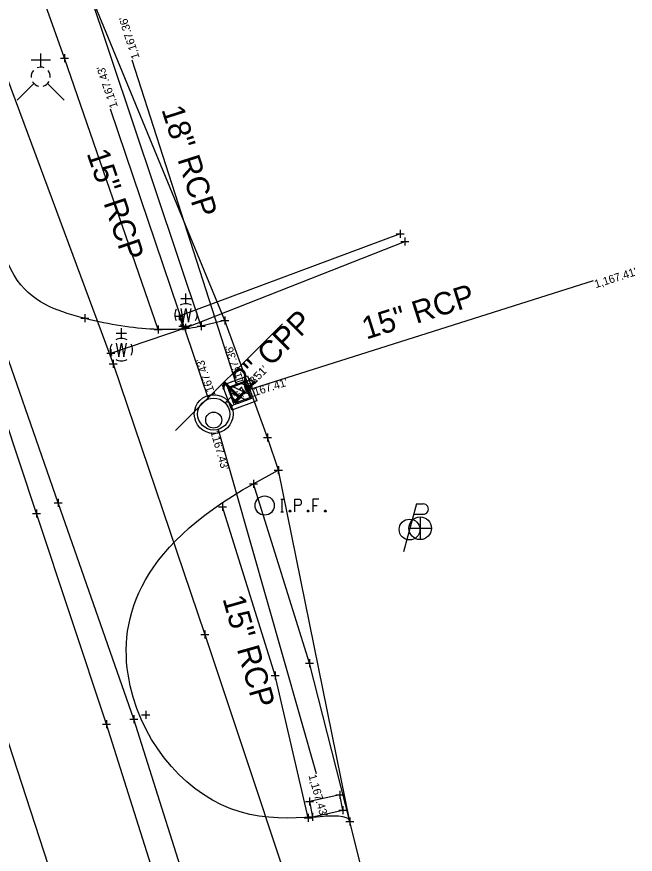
# Model space of a CAD drawing. Extents: x 2324380 to 2325559, y 691096 to 693386.
# Drawn here: x 2325067.6 to 2325144.8, y 692170 to 692274.6 of the extents above; entities that cross this region are included whole.
import ezdxf

# ---------------------------------------------------------------- set-up
doc = ezdxf.new("R2010")
doc.units = 0
for name, color, linetype in [('DR_X_Cells', 7, 'Continuous'), ('DR_X_Storm_Sewer', 7, 'Continuous'), ('DR_X_Text', 7, 'Continuous'), ('GK_Drainage_Nodes', 7, 'Continuous'), ('PM_X_CL_Double_Solid', 7, 'Continuous'), ('PM_X_Transverse_Line', 7, 'Continuous'), ('PV_X_COP', 7, 'Continuous'), ('PV_X_Driveway', 7, 'Continuous'), ('PV_X_EOP', 7, 'Continuous'), ('PV_X_Walk', 7, 'Continuous'), ('RD_X_Concrete_Pad', 7, 'Continuous'), ('SC_Scratch1', 7, 'Continuous'), ('SV_X_Control_Cells_Found', 7, 'Continuous'), ('SV_X_Mon_Cells_Found', 7, 'Continuous'), ('SV_X_Shot_Marker', 7, 'Continuous'), ('SV_X_Terrain_Boundary', 7, 'Continuous'), ('UT_X_Electric_Cells', 7, 'Continuous'), ('UT_X_Water', 7, 'Continuous'), ('UT_X_Water_Cells', 7, 'Continuous')]:
    doc.layers.add(name, color=color, linetype=linetype)

msp = doc.modelspace()

# ---------------------------------------------------------------- linework, layer by layer
at = {"layer": 'DR_X_Cells'}
for p, q in [((2325094.44, 692228.44), (2325096.7, 692227.4)), ((2325095.5, 692228.83), (2325096.3, 692228.46)), ((2325094.14, 692227.69), (2325096.32, 692226.69)), ((2325094.54, 692226.63), (2325095.26, 692226.3))]:
    msp.add_line(p, q, dxfattribs=at)
for points in [[(2325096.39, 692229.72), (2325097.55, 692226.59), (2325094.43, 692225.43), (2325093.27, 692228.56)], [(2325096.08, 692229.05), (2325096.88, 692226.9), (2325094.73, 692226.1), (2325093.94, 692228.25)], [(2325096, 692228.86), (2325096.69, 692226.98), (2325094.82, 692226.29), (2325094.12, 692228.16)]]:
    msp.add_lwpolyline(points, close=True, dxfattribs=at)
for centre, radius in [((2325092.18, 692224.94), 2.42), ((2325092.18, 692224.94), 2), ((2325092.18, 692224.19), 1)]:
    msp.add_circle(centre, radius, dxfattribs=at)
at = {"layer": 'DR_X_Storm_Sewer'}
for p, q in [((2325095.06, 692228.51), (2325081.99, 692269.16)), ((2325091.54, 692226.83), (2325079.28, 692263.03)), ((2325096.35, 692227.92), (2325139.58, 692241.61)), ((2325093.6, 692226.35), (2325094.47, 692227.23)), ((2325092.73, 692223.02), (2325104.96, 692180.06))]:
    msp.add_line(p, q, dxfattribs=at)
at = {"layer": 'DR_X_Text'}
msp.add_line((2325100.78, 692236.22), (2325087.43, 692222.88), dxfattribs=at)
at = {"layer": 'GK_Drainage_Nodes'}
for p, q in [((2325095.06, 692228.51), (2325095.06, 692228.51)), ((2325096.97, 692228.15), (2325096.97, 692228.15)), ((2325094.47, 692227.23), (2325094.47, 692227.23)), ((2325095.41, 692227.57), (2325095.41, 692227.57)), ((2325095.41, 692227.57), (2325095.41, 692227.57)), ((2325095.41, 692227.57), (2325095.41, 692227.57)), ((2325096.35, 692227.92), (2325096.35, 692227.92)), ((2325092.18, 692226.94), (2325092.18, 692226.94)), ((2325093.85, 692226.99), (2325093.85, 692226.99)), ((2325095.76, 692226.64), (2325095.76, 692226.64)), ((2325092.18, 692224.94), (2325092.18, 692224.94)), ((2325092.18, 692224.94), (2325092.18, 692224.94)), ((2325092.18, 692224.19), (2325092.18, 692224.19)), ((2325092.18, 692222.94), (2325092.18, 692222.94))]:
    msp.add_line(p, q, dxfattribs=at)
msp.add_circle((2325092.18, 692224.94), 2, dxfattribs=at)
at = {"layer": 'PM_X_CL_Double_Solid'}
msp.add_lwpolyline([(2325089.48, 692110.68), (2325084.32, 692128.51), (2325075.39, 692156.76), (2325066.63, 692183.78), (2325058.11, 692209.28), (2325049.62, 692233.9), (2325041.55, 692256.48), (2325033.1, 692279.67), (2325023.32, 692305.87), (2325013.77, 692329.93)], dxfattribs=at)
at = {"layer": 'PM_X_Transverse_Line'}
msp.add_lwpolyline([(2325119.99, 692049.57), (2325112.24, 692077.64), (2325103.35, 692107.53), (2325096.49, 692131.33), (2325087.35, 692159.17), (2325078.82, 692186.21), (2325070.07, 692212.52), (2325061.8, 692237.43), (2325045.09, 692283.67), (2325035.69, 692308.59), (2325025.65, 692334.45)], dxfattribs=at)
at = {"layer": 'PV_X_COP'}
msp.add_lwpolyline([(2325108.45, 692046.03), (2325099.34, 692075.66), (2325091, 692105.35), (2325084.32, 692128.51), (2325075.39, 692156.76), (2325066.63, 692183.78), (2325058.11, 692209.28), (2325049.62, 692233.9), (2325041.55, 692256.48), (2325033.1, 692279.67), (2325023.32, 692305.87), (2325013.77, 692329.93)], dxfattribs=at)
at = {"layer": 'PV_X_Driveway'}
for p, q in [((2325093.57, 692236.62), (2325090.6, 692235.9)), ((2325098.88, 692222), (2325093.57, 692236.62)), ((2325100.28, 692217.91), (2325098.88, 692222)), ((2325097.15, 692216.23), (2325100.24, 692217.94)), ((2325100.24, 692217.94), (2325100.28, 692217.91)), ((2325110.91, 692166.99), (2325109.19, 692174.04))]:
    msp.add_line(p, q, dxfattribs=at)
for points in [[(2325090.6, 692235.9), (2325088.84, 692235.48), (2325083.93, 692235.28), (2325075.21, 692236.84), (2325065.59, 692240.39), (2325064.41, 692252.96), (2325061.43, 692251.66)], [(2325109.19, 692174.04), (2325108.77, 692175.78), (2325094.85, 692170.95), (2325077.79, 692189.42), (2325082.29, 692208.02), (2325097.15, 692216.23)]]:
    msp.add_open_spline(points, degree=3, dxfattribs=at)
at = {"layer": 'PV_X_EOP'}
msp.add_lwpolyline([(2325123.25, 692051.46), (2325115.82, 692078.51), (2325110.86, 692095.71), (2325106.46, 692109.57), (2325099.73, 692132.13), (2325090.5, 692160.58), (2325082.22, 692186.84), (2325072.77, 692213.83), (2325064.19, 692238.4), (2325059.92, 692251), (2325055.34, 692262.57), (2325047.32, 692284.59), (2325037.78, 692309.71), (2325028.4, 692335.51)], dxfattribs=at)
at = {"layer": 'PV_X_Walk'}
for points in [[(2325090.6, 692235.9), (2325076.53, 692278.08), (2325068.46, 692300.04), (2325060.86, 692317.44), (2325050.46, 692344.77)], [(2325085.26, 692235.48), (2325073.57, 692269.38), (2325065.48, 692291.96), (2325056.49, 692315.71), (2325046.07, 692343.18)], [(2325109.19, 692174.04), (2325104.12, 692193.82), (2325097.15, 692216.23)], [(2325103.96, 692174.49), (2325099.86, 692192.28), (2325093.3, 692213.33)]]:
    msp.add_lwpolyline(points, dxfattribs=at)
at = {"layer": 'RD_X_Concrete_Pad'}
msp.add_lwpolyline([(2325104.13, 692176.55), (2325104.52, 692174.62), (2325108.32, 692175.44), (2325107.94, 692177.39)], close=True, dxfattribs=at)
at = {"layer": 'SV_X_Control_Cells_Found'}
for p, q in [((2325117.96, 692212.08), (2325117.96, 692209.26)), ((2325116.55, 692210.67), (2325119.37, 692210.67))]:
    msp.add_line(p, q, dxfattribs=at)
msp.add_circle((2325117.96, 692210.67), 1.41, dxfattribs=at)
at = {"layer": 'SV_X_Mon_Cells_Found'}
for points in [[(2325100.55, 692214.31), (2325100.91, 692214.31)], [(2325100.73, 692212.71), (2325100.73, 692214.31)], [(2325102.3, 692212.71), (2325102.3, 692214.31), (2325102.83, 692214.31), (2325102.88, 692214.29), (2325102.96, 692214.27), (2325102.99, 692214.24), (2325103.02, 692214.22), (2325103.07, 692214.16), (2325103.1, 692214.09), (2325103.12, 692213.99), (2325103.12, 692213.84), (2325103.11, 692213.79), (2325103.09, 692213.71), (2325103.05, 692213.63), (2325103, 692213.59), (2325102.97, 692213.56), (2325102.91, 692213.54), (2325102.83, 692213.53), (2325102.3, 692213.53)], [(2325105.31, 692214.31), (2325104.54, 692214.31), (2325104.54, 692212.71)], [(2325104.54, 692213.53), (2325105.08, 692213.53)], [(2325100.55, 692212.71), (2325100.91, 692212.71)], [(2325101.69, 692212.92), (2325101.74, 692212.92), (2325101.78, 692212.9), (2325101.81, 692212.84), (2325101.81, 692212.78), (2325101.78, 692212.73), (2325101.74, 692212.71), (2325101.69, 692212.71), (2325101.66, 692212.73), (2325101.62, 692212.78), (2325101.62, 692212.84), (2325101.66, 692212.9), (2325101.69, 692212.92)], [(2325103.94, 692212.92), (2325103.99, 692212.92), (2325104.03, 692212.9), (2325104.06, 692212.84), (2325104.06, 692212.78), (2325104.03, 692212.73), (2325103.99, 692212.71), (2325103.94, 692212.71), (2325103.91, 692212.73), (2325103.87, 692212.78), (2325103.87, 692212.84), (2325103.91, 692212.9), (2325103.94, 692212.92)], [(2325106.09, 692212.92), (2325106.14, 692212.92), (2325106.18, 692212.9), (2325106.21, 692212.84), (2325106.21, 692212.78), (2325106.18, 692212.73), (2325106.14, 692212.71), (2325106.09, 692212.71), (2325106.05, 692212.73), (2325106.02, 692212.78), (2325106.02, 692212.84), (2325106.05, 692212.9), (2325106.09, 692212.92)]]:
    msp.add_lwpolyline(points, dxfattribs=at)
msp.add_circle((2325098.54, 692213.51), 1.2, dxfattribs=at)
at = {"layer": 'SV_X_Shot_Marker'}
for p, q in [((2325073.07, 692269.38), (2325074.07, 692269.38)), ((2325073.57, 692269.88), (2325073.57, 692268.88)), ((2325073.57, 692269.38), (2325073.57, 692269.38)), ((2325114.95, 692247.46), (2325115.95, 692247.46)), ((2325115.45, 692247.96), (2325115.45, 692246.96)), ((2325115.45, 692247.46), (2325115.45, 692247.46)), ((2325115.52, 692246.48), (2325116.52, 692246.48)), ((2325116.02, 692246.98), (2325116.02, 692245.98)), ((2325116.02, 692246.48), (2325116.02, 692246.48)), ((2325087.89, 692237.67), (2325087.89, 692236.67)), ((2325075.6, 692236.93), (2325076.6, 692236.93)), ((2325076.1, 692237.43), (2325076.1, 692236.43)), ((2325076.1, 692236.93), (2325076.1, 692236.93)), ((2325087.39, 692237.17), (2325088.39, 692237.17)), ((2325087.89, 692237.17), (2325087.89, 692237.17)), ((2325093.07, 692236.62), (2325094.07, 692236.62)), ((2325093.57, 692237.12), (2325093.57, 692236.12)), ((2325093.57, 692236.62), (2325093.57, 692236.62)), ((2325084.76, 692235.48), (2325085.76, 692235.48)), ((2325084.76, 692235.48), (2325085.76, 692235.48)), ((2325085.26, 692235.98), (2325085.26, 692234.98)), ((2325085.26, 692235.98), (2325085.26, 692234.98)), ((2325085.26, 692235.48), (2325085.26, 692235.48)), ((2325085.26, 692235.48), (2325085.26, 692235.48)), ((2325087.83, 692235.92), (2325088.83, 692235.92)), ((2325088.15, 692235.72), (2325089.15, 692235.72)), ((2325088.33, 692236.42), (2325088.33, 692235.42)), ((2325088.33, 692235.92), (2325088.33, 692235.92)), ((2325088.65, 692236.22), (2325088.65, 692235.22)), ((2325088.65, 692235.72), (2325088.65, 692235.72)), ((2325090.1, 692235.9), (2325091.1, 692235.9)), ((2325090.1, 692235.9), (2325091.1, 692235.9)), ((2325090.6, 692236.4), (2325090.6, 692235.4)), ((2325090.6, 692236.4), (2325090.6, 692235.4)), ((2325090.6, 692235.9), (2325090.6, 692235.9)), ((2325090.6, 692235.9), (2325090.6, 692235.9)), ((2325078.84, 692232.54), (2325079.84, 692232.54)), ((2325079.34, 692233.04), (2325079.34, 692232.04)), ((2325079.34, 692232.54), (2325079.34, 692232.54)), ((2325079.64, 692231.7), (2325079.64, 692230.7)), ((2325079.14, 692231.2), (2325080.14, 692231.2)), ((2325079.64, 692231.2), (2325079.64, 692231.2)), ((2325098.38, 692222), (2325099.38, 692222)), ((2325098.88, 692222.5), (2325098.88, 692221.5)), ((2325098.88, 692222), (2325098.88, 692222)), ((2325099.74, 692217.94), (2325100.74, 692217.94)), ((2325099.78, 692217.91), (2325100.78, 692217.91)), ((2325100.24, 692218.44), (2325100.24, 692217.44)), ((2325100.24, 692217.94), (2325100.24, 692217.94)), ((2325100.28, 692218.41), (2325100.28, 692217.41)), ((2325100.28, 692217.91), (2325100.28, 692217.91)), ((2325097.15, 692216.73), (2325097.15, 692215.73)), ((2325097.15, 692216.73), (2325097.15, 692215.73)), ((2325096.65, 692216.23), (2325097.65, 692216.23)), ((2325096.65, 692216.23), (2325097.65, 692216.23)), ((2325097.15, 692216.23), (2325097.15, 692216.23)), ((2325097.15, 692216.23), (2325097.15, 692216.23)), ((2325072.27, 692213.83), (2325073.27, 692213.83)), ((2325072.77, 692214.33), (2325072.77, 692213.33)), ((2325072.77, 692213.83), (2325072.77, 692213.83)), ((2325093.3, 692213.83), (2325093.3, 692212.83)), ((2325069.57, 692212.52), (2325070.57, 692212.52)), ((2325070.07, 692213.02), (2325070.07, 692212.02)), ((2325070.07, 692212.52), (2325070.07, 692212.52)), ((2325092.8, 692213.33), (2325093.8, 692213.33)), ((2325093.3, 692213.33), (2325093.3, 692213.33)), ((2325091.06, 692197.91), (2325091.06, 692196.91)), ((2325090.56, 692197.41), (2325091.56, 692197.41)), ((2325091.06, 692197.41), (2325091.06, 692197.41)), ((2325103.62, 692193.82), (2325104.62, 692193.82)), ((2325104.12, 692194.32), (2325104.12, 692193.32)), ((2325104.12, 692193.82), (2325104.12, 692193.82)), ((2325099.86, 692192.78), (2325099.86, 692191.78)), ((2325099.36, 692192.28), (2325100.36, 692192.28)), ((2325099.86, 692192.28), (2325099.86, 692192.28)), ((2325083.19, 692187.38), (2325084.19, 692187.38)), ((2325083.69, 692187.88), (2325083.69, 692186.88)), ((2325083.69, 692187.38), (2325083.69, 692187.38)), ((2325078.82, 692186.71), (2325078.82, 692185.71)), ((2325081.72, 692186.84), (2325082.72, 692186.84)), ((2325082.22, 692187.34), (2325082.22, 692186.34)), ((2325082.22, 692186.84), (2325082.22, 692186.84)), ((2325078.32, 692186.21), (2325079.32, 692186.21)), ((2325078.82, 692186.21), (2325078.82, 692186.21)), ((2325104.13, 692177.05), (2325104.13, 692176.05)), ((2325107.44, 692177.39), (2325108.44, 692177.39)), ((2325107.94, 692177.89), (2325107.94, 692176.89)), ((2325107.94, 692177.39), (2325107.94, 692177.39)), ((2325103.63, 692176.55), (2325104.63, 692176.55)), ((2325104.13, 692176.55), (2325104.13, 692176.55)), ((2325108.32, 692175.94), (2325108.32, 692174.94)), ((2325103.96, 692174.99), (2325103.96, 692173.99)), ((2325103.96, 692174.99), (2325103.96, 692173.99)), ((2325104.52, 692175.12), (2325104.52, 692174.12)), ((2325107.82, 692175.44), (2325108.82, 692175.44)), ((2325108.32, 692175.44), (2325108.32, 692175.44)), ((2325103.46, 692174.49), (2325104.46, 692174.49)), ((2325103.46, 692174.49), (2325104.46, 692174.49)), ((2325103.96, 692174.49), (2325103.96, 692174.49)), ((2325103.96, 692174.49), (2325103.96, 692174.49)), ((2325104.02, 692174.62), (2325105.02, 692174.62)), ((2325104.52, 692174.62), (2325104.52, 692174.62)), ((2325108.69, 692174.04), (2325109.69, 692174.04)), ((2325108.69, 692174.04), (2325109.69, 692174.04)), ((2325109.19, 692174.54), (2325109.19, 692173.54)), ((2325109.19, 692174.54), (2325109.19, 692173.54)), ((2325109.19, 692174.04), (2325109.19, 692174.04)), ((2325109.19, 692174.04), (2325109.19, 692174.04))]:
    msp.add_line(p, q, dxfattribs=at)
at = {"layer": 'SV_X_Terrain_Boundary'}
msp.add_lwpolyline([(2325110.91, 692166.99), (2325109.19, 692174.04), (2325100.28, 692217.91), (2325098.88, 692222), (2325093.57, 692236.62), (2325076.53, 692278.08), (2325068.46, 692300.04), (2325060.86, 692317.44), (2325050.46, 692344.77), (2325046.07, 692343.18), (2325028.4, 692335.51), (2325013.77, 692329.93), (2324997.75, 692325.76), (2324994.77, 692324.28), (2324978.96, 692319.34), (2325000.08, 692267.16), (2325014.61, 692222.14), (2325030.56, 692121.28)], dxfattribs=at)
at = {"layer": 'UT_X_Electric_Cells'}
for p, q in [((2325117.49, 692213.71), (2325115.88, 692207.71)), ((2325117.49, 692213.71), (2325118.34, 692213.71)), ((2325117.15, 692212.43), (2325118.34, 692212.43))]:
    msp.add_line(p, q, dxfattribs=at)
msp.add_circle((2325116.63, 692210.51), 1.3, dxfattribs=at)
msp.add_arc((2325118.35, 692213.07), 0.638, 268.8767, 91.1233, dxfattribs=at)
at = {"layer": 'UT_X_Water'}
for points in [[(2324934.92, 692571.2), (2324956.29, 692529.58), (2324976.21, 692488), (2324991.94, 692453.33), (2325012.4, 692405.82), (2325031.94, 692356.27), (2325051.28, 692307.99), (2325065.92, 692268.22), (2325079.64, 692231.2), (2325091.06, 692197.41), (2325105.98, 692152.66), (2325121.62, 692099.73), (2325124.52, 692091.67), (2325134.64, 692057.74)], [(2325115.45, 692247.46), (2325087.89, 692237.17), (2325088.33, 692235.92)], [(2325079.34, 692232.54), (2325088.65, 692235.72), (2325116.02, 692246.48)]]:
    msp.add_lwpolyline(points, dxfattribs=at)
at = {"layer": 'UT_X_Water_Cells'}
for p, q in [((2325071.79, 692269.13), (2325069.39, 692269.13)), ((2325070.59, 692268.27), (2325070.59, 692269.99)), ((2325070.59, 692267.07), (2325070.59, 692267.07)), ((2325070.59, 692267.07), (2325070.59, 692267.07)), ((2325069.74, 692266.22), (2325067.66, 692264.14)), ((2325071.43, 692266.22), (2325073.51, 692264.14)), ((2325088.71, 692238.72), (2325088.71, 692239.99)), ((2325089.35, 692239.35), (2325088.08, 692239.35)), ((2325088.71, 692237.32), (2325088.71, 692237.32)), ((2325080.66, 692234.38), (2325080.66, 692235.65)), ((2325081.29, 692235.02), (2325080.02, 692235.02)), ((2325080.66, 692232.98), (2325080.66, 692232.98))]:
    msp.add_line(p, q, dxfattribs=at)
for points in [[(2325088.08, 692238.14), (2325088.39, 692236.41), (2325088.71, 692238.14), (2325089.03, 692236.41), (2325089.35, 692238.14)], [(2325080.02, 692233.8), (2325080.34, 692232.08), (2325080.66, 692233.8), (2325080.98, 692232.08), (2325081.29, 692233.8)]]:
    msp.add_lwpolyline(points, dxfattribs=at)
for centre, radius, start, end in [((2325070.59, 692267.07), 1.2, 68.1395, 112.038), ((2325070.59, 692267.07), 1.2, 140.021, 184.0629), ((2325070.59, 692267.07), 1.2, 356.0165, 39.9889), ((2325070.59, 692267.07), 1.2, 211.8788, 255.8479), ((2325070.59, 692267.07), 1.2, 283.8239, 329.9097), ((2325088.71, 692237.32), 1.4, 60.0184, 120.0157), ((2325088.71, 692237.32), 1.4, 150.0184, 209.9816), ((2325088.71, 692237.32), 1.4, 330.0184, 29.9816), ((2325088.71, 692237.32), 1.4, 239.9843, 299.9816), ((2325080.66, 692232.98), 1.4, 150.0184, 209.9816), ((2325080.66, 692232.98), 1.4, 60.0184, 120.0157), ((2325080.66, 692232.98), 1.4, 330.0184, 29.9816), ((2325080.66, 692232.98), 1.4, 239.9843, 299.9816)]:
    msp.add_arc(centre, radius, start, end, dxfattribs=at)

# ---------------------------------------------------------------- texts
at = {"layer": 'DR_X_Text'}
for s, rotation, p in [('18" RCP', 287.8283, (2325085.63, 692262.99)), ('15" RCP', 288.7096, (2325076.3, 692257.52)), ('15" RCP', 17.5685, (2325111.23, 692234.23)), ('12" CPP', 44.9865, (2325094.67, 692226.15)), ('15" RCP', 285.8895, (2325093.26, 692201.89))]:
    msp.add_text(s, height=2.8, rotation=rotation, dxfattribs=at).set_placement(p)
at = {"layer": 'SC_Scratch1'}
for s, rotation, p in [("1,167.36'", 107.8283, (2325082.94, 692269.47)), ("1,167.43'", 108.7096, (2325080.23, 692263.35)), ("1,167.41'", 17.5685, (2325139.88, 692240.66)), ("1167.36'", 107.8283, (2325096.01, 692228.82)), ("1167.43'", 108.7096, (2325092.49, 692227.16)), ("1,167.51'", 44.9865, (2325095.18, 692226.52)), ("1167.68'", 44.9865, (2325094.31, 692225.65)), ("1167.41'", 17.5685, (2325096.65, 692226.97)), ("1167.43'", 285.8895, (2325091.77, 692222.74)), ("1,167.43'", 285.8895, (2325104, 692179.78))]:
    msp.add_text(s, height=1, rotation=rotation, dxfattribs=at).set_placement(p)

doc.saveas('drawing.dxf')
